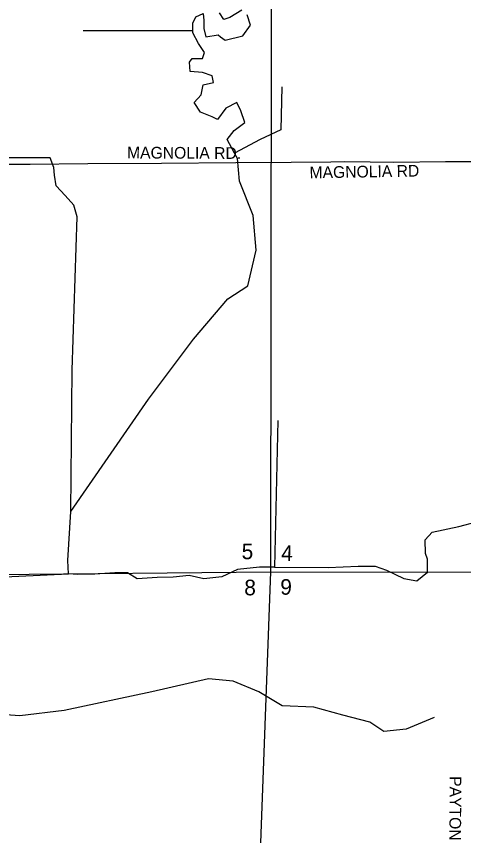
# Model space of a CAD drawing. Extents: x 1670563 to 1761545, y 515755 to 578944.
# Drawn here: x 1702877 to 1705739, y 558302 to 563544 of the extents above; entities that cross this region are included whole.
import ezdxf

# ---------------------------------------------------------------- set-up
doc = ezdxf.new("R2010")
doc.units = 0
for name, color, linetype in [('5_sectionlines', 7, 'Continuous'), ('62_text', 7, 'Continuous'), ('SHP_LINE', 7, 'Continuous'), ('STREETCL', 7, 'Continuous'), ('STRNAMES', 7, 'Continuous')]:
    doc.layers.add(name, color=color, linetype=linetype)

msp = doc.modelspace()

# ---------------------------------------------------------------- linework, layer by layer
at = {"layer": '5_sectionlines'}
for points in [[(1704407.6, 557333.3), (1704504.6, 559990.6), (1704511, 565220.7)], [(1677977.7, 559756.7), (1683296.8, 559793.9), (1688575.5, 559928.7), (1693867.8, 559919.3), (1699198.2, 559938), (1704504.6, 559990.6), (1709805, 559985.3), (1715121.2, 559943.8), (1715086.8, 558664.7)]]:
    msp.add_lwpolyline(points, dxfattribs=at)
at = {"layer": 'SHP_LINE'}
for points in [[(1704007, 563440), (1704007, 563502), (1704025, 563541), (1704073, 563563), (1704077, 563519), (1704077, 563467), (1704090, 563414), (1704169, 563427), (1704183, 563414), (1704213, 563392), (1704327, 563419), (1704376, 563489), (1704354, 563554)], [(1704319, 563585), (1704244, 563537), (1704205, 563524), (1704178, 563568)], [(1703305, 563454), (1704007, 563454)], [(1704274, 562669), (1704226, 562757), (1704270, 562814), (1704340, 562866), (1704314, 562941), (1704288, 562993), (1704218, 562958), (1704165, 562884), (1704130, 562901), (1704055, 562932), (1704016, 562993), (1704060, 563042), (1704073, 563107), (1704139, 563121), (1704130, 563164), (1704069, 563186), (1703990, 563191), (1703985, 563252), (1704003, 563274), (1704069, 563274), (1704082, 563313), (1704042, 563370), (1704007, 563440)], [(1704577, 563094), (1704569, 562818), (1704437, 562757), (1704274, 562669)], [(1703226, 560376), (1703723, 561094), (1704011, 561478), (1704231, 561737), (1704358, 561820), (1704411, 562048), (1704393, 562271), (1704305, 562491), (1704292, 562635), (1704274, 562669)], [(1703235, 561280), (1703266, 562262), (1703245, 562337), (1703189, 562399), (1703133, 562461), (1703121, 562529), (1703117, 562578), (1703093, 562640), (1703027, 562640), (1702810, 562640)], [(1703226, 560376), (1703235, 561280)], [(1704550, 560959), (1704530, 560020)], [(1703210, 559977), (1703207, 560062), (1703226, 560376)], [(1704530, 560020), (1704873, 560017), (1705064, 560027), (1705174, 560027), (1705246, 560001), (1705356, 559948), (1705440, 559933), (1705508, 559988), (1705508, 560071), (1705495, 560108), (1705493, 560194), (1705537, 560244), (1705709, 560281), (1705822, 560310)], [(1704530, 560020), (1704434, 560020), (1704292, 560006), (1704191, 559958), (1704076, 559946), (1703983, 559966), (1703880, 559957), (1703778, 559954), (1703651, 559945), (1703588, 559983), (1703508, 559984), (1703379, 559976), (1703271, 559974), (1703210, 559977)], [(1702086, 559155), (1702166, 559355), (1702180, 559419), (1702208, 559475), (1702266, 559506), (1702308, 559562), (1702323, 559627), (1702314, 559773), (1702334, 559864), (1702371, 559933), (1702451, 559948), (1702574, 559948), (1703210, 559977)], [(1705551, 559058), (1705371, 558983), (1705229, 558968), (1705139, 559028), (1704967, 559073), (1704780, 559125), (1704578, 559133), (1704429, 559222), (1704264, 559290), (1704107, 559305), (1703745, 559222), (1703184, 559102), (1702899, 559068), (1702602, 559089), (1702446, 559125), (1702319, 559127), (1702194, 559146), (1702086, 559155)]]:
    msp.add_lwpolyline(points, dxfattribs=at)
at = {"layer": 'STREETCL'}
for points in [[(1701915.2, 562598.2), (1701979.4, 562598.2), (1702164.1, 562598.2), (1702385.1, 562598.7), (1702858.6, 562599.2), (1702965.8, 562599.7), (1703333.6, 562602.3), (1703806.5, 562604.9), (1704282.5, 562608.5), (1704634.9, 562612.1)], [(1704634.9, 562612.1), (1704889.8, 562614.4), (1704979.7, 562615.5), (1705141.4, 562613.8), (1705293.1, 562612.2), (1705624.2, 562614.9), (1705838.8, 562616.6)]]:
    msp.add_lwpolyline(points, dxfattribs=at)

# ---------------------------------------------------------------- texts
at = {"layer": '62_text'}
for s, p in [('5', (1704318, 560071.5)), ('4', (1704571.1, 560060.7)), ('8', (1704334.8, 559840.4)), ('9', (1704565, 559844.3))]:
    msp.add_text(s, height=100, rotation=358.9284, dxfattribs=at).set_placement(p)
at = {"layer": 'STRNAMES'}
for s, rotation, p in [('MAGNOLIA RD.', 359.7449, (1703585.4, 562635.4)), ('MAGNOLIA RD', 0.9896, (1704753.8, 562507.8)), ('PAYTON LN', 269.6142, (1705650, 558682.8))]:
    msp.add_text(s, height=75, rotation=rotation, dxfattribs=at).set_placement(p)

doc.saveas('drawing.dxf')
